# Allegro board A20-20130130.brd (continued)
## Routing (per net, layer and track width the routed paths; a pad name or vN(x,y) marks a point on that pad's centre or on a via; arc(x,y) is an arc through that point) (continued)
DSCK-N: length 90.5
  TOP w0.114: U4.G7 93.19,56.88 92.88,56.88 92.76,56.76 92.76,56.06 91.46,54.76 90.96,54.76 90.68,55.05 90.68,55.99 90.81,56.12 90.81,57.82 91.16,58.16 92.14,58.16 92.62,58.65 92.62,60.38 92.51,60.49 92.11,60.49 91.98,60.36 v1(91.98,60.26) ; v1(108.92,57.82) 108.98,57.82 109.06,57.9 109.19,57.9 109.24,57.86 109.24,57.69 108.85,57.3 108.64,57.3 108.44,57.5 108.44,58.47 108.2,58.71 107.64,58.71 107.18,58.25 107.18,54.45 107.55,54.08 108,54.08 109.15,55.23 109.15,56.09 109.68,56.62 U3.G7 ; v1(83.48,57.06) 83.1,56.68 U5.G7 ; v1(120.1,57.02) 120.11,57.02 U2.G7 ; v1(101.06,64.91) 101.38,64.91 101.57,65.09 101.57,65.47 C3.1 101.64,66 101.62,66.01 R9.2
  BOTTOM w0.114: v1(120.1,57.02) 119.87,57.26 118.56,57.26 118.37,57.45 109.56,57.45 109.19,57.82 v1(108.92,57.82) 108.92,58.11 108.39,58.63 108.39,59.81 107.95,60.25 107.52,60.25 107.21,60.55 107.21,61.53 107.09,61.65 106.91,61.65 106.79,61.54 106.79,60.55 106.49,60.25 105.31,60.25 104.56,61 104.13,61 103.45,61.68 103.45,62.12 103.82,62.48 103.82,62.65 103.69,62.78 103.52,62.78 103.15,62.41 102.72,62.41 101.94,63.2 101.94,64.56 101.84,64.65 101.55,64.65 101.48,64.72 101.48,65.01 101.57,65.1 101.81,65.1 101.94,65.22 101.94,65.81 101.73,66.01 100.73,66.01 100.57,65.85 100.57,65.04 100.7,64.91 v1(101.06,64.91) 101.06,64.55 101.23,64.37 101.23,62.02 100.09,60.88 100.09,60.71 101.45,59.35 101.45,58.92 101.13,58.61 100.69,58.61 99.33,59.96 98.59,59.96 97.6,58.97 97.6,57.98 97.31,57.69 96.87,57.69 96.54,58.02 96.54,58.97 96.42,59.09 95.84,59.09 94.47,60.46 92.18,60.46 v1(91.98,60.26) 91.72,60.53 91.45,60.53 90.47,59.54 87.7,59.54 87.41,59.83 86.61,59.83 86.08,59.3 86.08,57.93 85.53,57.38 83.78,57.38 83.48,57.09 v1(83.48,57.06)
EFUSE-VDDQ: length 0.5
  TOP w0.254: U1.T9 v1(99.43,76.1)
EGCLKIN: length 2.8
  TOP w0.102: U1.D13 v1(89.08,80.05)
  BOTTOM w0.102: 87.02,80.47 88.67,80.47 89.08,80.07 v1(89.08,80.05)
EGTXCLK: length 0.5
  TOP w0.102: U1.E12 v1(89.88,78.5)
EMDC: length 0.5
  TOP w0.102: U1.E10 v1(89.88,76.9)
EMDIO: length 2.8
  TOP w0.102: U1.D11 v1(89.08,77.7)
  BOTTOM w0.102: 87.02,78.12 88.67,78.12 89.08,77.71 v1(89.08,77.7)
EPHY-RST-N: length 0.5
  TOP w0.102: U1.C13 v1(88.28,80.05)
ERXCLK: length 2.8
  TOP w0.102: U1.D9 v1(89.08,76.1)
  BOTTOM w0.102: 87.02,76.52 88.67,76.52 89.08,76.11 v1(89.08,76.1)
ERXD0: length 0.5
  TOP w0.102: U1.E6 v1(89.88,73.7)
ERXD1: length 2.8
  TOP w0.102: U1.D6 v1(89.08,73.7)
  BOTTOM w0.102: 87.02,74.12 88.67,74.12 89.08,73.71 v1(89.08,73.7)
ERXD2: length 0.5
  TOP w0.102: U1.E5 v1(89.88,72.9)
ERXD3: length 2.8
  TOP w0.102: U1.D5 v1(89.08,72.9)
  BOTTOM w0.102: 87.02,73.32 88.67,73.32 89.08,72.91 v1(89.08,72.9)
ERXDV: length 2.8
  TOP w0.102: U1.D10 v1(89.08,76.9)
  BOTTOM w0.102: v1(89.08,76.9) 89.08,76.91 88.67,77.32 87.02,77.32
ESREXT: length 5.2
  TOP w0.102: U1.V21 v1(101.03,86.45)
  BOTTOM w0.102: 101.03,89.71 v1(101.03,86.45)
  BOTTOM w0.127: 101.03,91.12 101.03,89.71
ESRXM: length 1.5
  TOP w0.102: U1.U20 v1(100.23,85.65)
  BOTTOM w0.114: 99.84,86.49 99.84,86.48 99.84,86.04 v1(100.23,85.65)
ESRXP: length 0.6
  TOP w0.102: U1.U21 v1(100.23,86.45)
  BOTTOM w0.114: 100.16,86.52 v1(100.23,86.45)
ESTXM: length 4.9
  TOP w0.102: U1.T21 v1(99.43,86.45)
  BOTTOM w0.114: 98.94,90.59 99.33,90.19 99.33,86.55 v1(99.43,86.45)
ESTXP: length 5.7
  TOP w0.102: U1.T20 v1(99.43,85.65)
  BOTTOM w0.114: v1(99.43,85.65) 99.02,86.07 99.02,90.06 98.62,90.46
ESVDD1V2: length 1.1
  TOP w0.254: U1.M16 v1(95.48,82.45) ; U1.M15 v1(95.48,81.65)
ESVDD2V5: length 1.1
  TOP w0.254: U1.N16 v1(97.03,82.45) ; U1.N15 v1(97.03,81.65)
ETXD0: length 0.5
  TOP w0.102: U1.E8 v1(89.88,75.3)
ETXD1: length 2.8
  TOP w0.102: U1.D8 v1(89.08,75.3)
  BOTTOM w0.102: v1(89.08,75.3) 89.08,75.31 88.67,75.72 87.02,75.72
ETXD2: length 0.5
  TOP w0.102: U1.E7 v1(89.88,74.5)
ETXD3: length 2.8
  TOP w0.102: U1.D7 v1(89.08,74.5)
  BOTTOM w0.102: 87.02,74.92 88.67,74.92 89.08,74.51 v1(89.08,74.5)
ETXEN: length 0.5
  TOP w0.102: U1.E11 v1(89.88,77.7)
FMINL: length 2.8
  TOP w0.102: U1.Y20 v1(102.63,85.65)
  BOTTOM w0.102: v1(102.63,85.65) 102.63,85.64 103.04,85.23 104.69,85.23
FMINR: length 2.8
  TOP w0.102: U1.Y21 v1(102.63,86.45)
  BOTTOM w0.102: 104.69,86.03 103.04,86.03 102.63,86.44 v1(102.63,86.45)
GS-INT1: length 11.7
  TOP w0.102: 77.96,80.37 84.25,74.08 U1.A6
GY-INT1: length 0.5
  TOP w0.102: U1.C2 v1(88.28,70.5)
GY-INT2: length 14.2
  TOP w0.102: 76.34,71.39 81.74,71.39 83.37,69.76 86.7,69.76 87.09,69.36 88.73,69.36 89.45,70.08 U1.D1
HCEC: length 7.9
  TOP w0.102: 97.45,89.72 U1.P23
  TOP w0.127: 97.45,95.57 97.45,89.72
HHPD: length 8.9
  TOP w0.102: 97.87,89.72 97.87,87.27 97.86,87.26 97.83,87.26 U1.P22
  TOP w0.127: 97.87,89.72 97.87,95.57
HPBP: length 4.1
  TOP w0.102: U1.AC19 108.8,84.48
HPCOM: length 4.4
  TOP w0.102: U1.AA20 v1(103.43,85.65) ; U1.AA19 v1(103.43,84.85)
  BOTTOM w0.102: v1(103.43,84.85) 105.09,84.85 ; v1(103.43,85.65) 105.09,85.65
HPL: length 5
  TOP w0.178: U1.Y19 102.26,84.48 102.63,84.85 v1(102.63,84.85)
  BOTTOM w0.178: v1(102.63,84.85) 103.05,84.43 106.96,84.43
HPR: length 6
  TOP w0.178: v1(101.83,84.85) 101.83,84.82 101.49,84.48 U1.W19
  BOTTOM w0.178: 106.96,83.98 102.86,83.98 102.45,84.39 102.29,84.39 v1(101.83,84.85)
HPVCC: length 7.3
  TOP w0.102: 108.8,84.86 104.23,84.86 U1.AB19
  TOP w0.254: U1.J14 v1(93.06,80.87) U1.H15 ; U1.H9 v1(92.28,76.1) ; U1.J9 v1(93.08,76.1)
HSCL: length 7.9
  TOP w0.102: 98.25,89.72 U1.R23
  TOP w0.127: 98.25,95.57 98.25,89.72
HSDA: length 8.9
  TOP w0.102: 98.67,89.72 98.67,87.27 98.66,87.26 98.63,87.26 U1.R22
  TOP w0.127: 98.67,89.72 98.67,95.57
HTX0N: length 12.9
  TOP w0.114: 101.93,99.26 101.07,98.4 101.07,87.29 U1.V22
HTX0P: length 12.1
  TOP w0.114: U1.V23 100.75,87.78 100.75,98.53 101.61,99.39
HTX1N: length 0.6
  TOP w0.114: U1.U22 100.27,87.29
HTX1P: length 0.1
  TOP w0.114: 99.95,87.78 U1.U23
HTX2N: length 13
  TOP w0.114: U1.T22 99.44,87.26 99.44,98.76 98.78,99.41
HTX2P: length 11.9
  TOP w0.114: U1.T23 99.12,87.74 99.12,98.63 98.47,99.28
HTXCN: length 12.2
  TOP w0.114: U1.W22 101.87,87.29 101.87,97.43 102.92,98.48
HTXCP: length 11.4
  TOP w0.114: 102.6,98.61 101.55,97.56 101.55,87.78 U1.W23
HVP: length 0.5
  TOP w0.254: U1.T13 v1(99.43,80.05)
HVREGIO1: length 0.5
  TOP w0.254: U1.T14 v1(99.43,80.85)
I2S1-BCLK: length 0.5
  TOP w0.102: U1.D12 v1(89.08,78.5)
I2S1-MCLK: length 0.5
  TOP w0.102: U1.E9 v1(89.88,76.1)
IR-RX: length 10.4
  TOP w0.102: U1.A13 85.45,79.68 80.19,84.94 80.19,86.31
JTAG-CK: length 10.9
  TOP w0.102: 79.42,83.26 85,77.68 87.45,77.68 U1.B10
JTAG-DI: length 12.6
  TOP w0.102: U1.B9 87.43,76.9 84.77,76.9 78.13,83.54
JTAG-DO: length 12
  TOP w0.102: 77.83,83.28 84.63,76.48 U1.A9
JTAG-MS: length 11.4
  TOP w0.102: 78.35,83.8 84.88,77.28 U1.A10
JTAG-SEL: length 0.5
  TOP w0.254: U1.T10 v1(99.43,76.9)
LCD0-BL-EN: length 11.9
  TOP w0.102: U1.B4 87.59,72.48 87.21,72.85 84.05,72.85 78.4,78.5
LCD0-CLK: length 0.5
  TOP w0.102: U1.Y9 v1(102.63,76.1)
LCD0-D0: length 5.1
  TOP w0.102: U1.AB15 104.23,81.66 108.8,81.66
LCD0-D1: length 4.1
  TOP w0.102: U1.AC15 108.8,81.28
LCD0-D2: length 5.1
  TOP w0.102: 108.8,80.86 104.23,80.86 U1.AB14
LCD0-D3: length 4.1
  TOP w0.102: U1.AC14 108.8,80.48
LCD0-D4: length 5.1
  TOP w0.102: 108.8,80.06 104.23,80.06 U1.AB13
LCD0-D5: length 4.1
  TOP w0.102: U1.AC13 108.8,79.68
LCD0-D6: length 5.1
  TOP w0.102: U1.AB12 104.23,79.26 108.8,79.26
LCD0-D7: length 4.1
  TOP w0.102: U1.AC12 108.8,78.88
LCD0-D8: length 5.1
  TOP w0.102: 108.8,78.46 104.23,78.46 U1.AB11
LCD0-D9: length 4.1
  TOP w0.102: U1.AC11 108.8,78.08
LCD0-D10: length 0.5
  TOP w0.102: U1.Y15 v1(102.63,81.65)
LCD0-D11: length 2.2
  TOP w0.102: U1.AA15 v1(103.43,81.65)
  BOTTOM w0.102: v1(103.43,81.65) 105.09,81.65
LCD0-D12: length 2.8
  TOP w0.102: U1.Y14 v1(102.63,80.85)
  BOTTOM w0.102: 104.69,80.43 103.04,80.43 102.63,80.84 v1(102.63,80.85)
LCD0-D13: length 0.5
  TOP w0.102: U1.AA14 v1(103.43,80.85)
LCD0-D14: length 0.5
  TOP w0.102: U1.Y13 v1(102.63,80.05)
LCD0-D15: length 2.2
  TOP w0.102: U1.AA13 v1(103.43,80.05)
  BOTTOM w0.102: v1(103.43,80.05) 105.09,80.05
LCD0-D16: length 2.8
  TOP w0.102: U1.Y12 v1(102.63,78.5)
  BOTTOM w0.102: 104.69,78.08 103.04,78.08 102.63,78.49 v1(102.63,78.5)
LCD0-D17: length 0.5
  TOP w0.102: U1.AA12 v1(103.43,78.5)
LCD0-D18: length 2.8
  TOP w0.102: U1.Y11 v1(102.63,77.7)
  BOTTOM w0.102: 104.69,77.28 103.04,77.28 102.63,77.69 v1(102.63,77.7)
LCD0-D19: length 2.2
  TOP w0.102: U1.AA11 v1(103.43,77.7)
  BOTTOM w0.102: v1(103.43,77.7) 105.09,77.7
LCD0-D20: length 2.8
  TOP w0.102: U1.Y10 v1(102.63,76.9)
  BOTTOM w0.102: v1(102.63,76.9) 102.63,76.89 103.04,76.48 104.69,76.48
LCD0-D21: length 2.2
  TOP w0.102: U1.AA10 v1(103.43,76.9)
  BOTTOM w0.102: v1(103.43,76.9) 105.09,76.9
LCD0-D22: length 5.1
  TOP w0.102: U1.AB10 104.23,77.66 108.8,77.66
LCD0-D23: length 4.1
  TOP w0.102: U1.AC10 108.8,77.28
LCD0-DE: length 2.2
  TOP w0.102: U1.AA9 v1(103.43,76.1)
  BOTTOM w0.102: v1(103.43,76.1) 105.09,76.1
LCD0-HSYNC: length 5.1
  TOP w0.102: 108.8,76.86 104.23,76.86 U1.AB9
LCD0-PWR: length 2.2
  TOP w0.102: U1.C4 v1(88.28,72.1)
  BOTTOM w0.102: v1(88.28,72.1) 86.62,72.1
LCD0-SCK: length 2.2
  TOP w0.102: U1.C11 v1(88.28,77.7)
  BOTTOM w0.102: v1(88.28,77.7) 86.62,77.7
LCD0-SDA: length 2.2
  TOP w0.102: U1.C10 v1(88.28,76.9)
  BOTTOM w0.102: v1(88.28,76.9) 86.62,76.9
LCD0-VSYNC: length 4.1
  TOP w0.102: U1.AC9 108.8,76.48
LINEINL: length 0.7
  TOP w0.178: 104.41,85.66 104.02,85.28 U1.AB20
LINEINR: length 0.4
  TOP w0.178: U1.AB21 104.03,86.08 104.07,86.12 104.24,86.12
LRADC0: length 7.8
  TOP w0.102: 104.07,89.72 104.07,87.89 U1.AB23
  TOP w0.254: 104.07,95.36 104.07,89.72
LS-INT: length 2.8
  TOP w0.102: U1.D2 v1(89.08,70.5)
  BOTTOM w0.102: v1(89.08,70.5) 89.08,70.51 88.67,70.92 87.02,70.92
MIC1OUTN: length 7.9
  TOP w0.102: 104.65,89.72 U1.AC23
  TOP w0.127: 104.65,95.57 104.65,89.72
MICIN1: length 4.1
  TOP w0.102: U1.AC20 108.8,85.28
MICIN2: length 0.7
  TOP w0.102: U1.AC21 v1(105.38,86.08)
NALE: length 8.9
  TOP w0.102: 96.27,89.72 96.27,87.27 96.26,87.26 96.23,87.26 U1.M22
  TOP w0.127: 96.27,89.72 96.27,95.57
NAND-VCC: length 1.1
  TOP w0.102: U1.H19 v1(92.28,84.85) ; U1.J19 v1(93.08,84.85)
NCE0-N: length 7.9
  TOP w0.102: 94.25,89.72 U1.K23
  TOP w0.127: 94.25,95.57 94.25,89.72
NCE1-N: length 8.9
  TOP w0.102: U1.L22 95.47,87.3 95.47,89.72
  TOP w0.127: 95.47,95.57 95.47,89.72
NCE2-N: length 7.9
  TOP w0.102: 91.05,89.72 U1.F23
  TOP w0.127: 91.05,95.57 91.05,89.72
NCE3-N: length 8.9
  TOP w0.102: 91.45,89.72 91.45,87.27 U1.F22
  TOP w0.127: 91.45,89.72 91.45,95.57
NCLE: length 7.9
  TOP w0.102: 95.05,89.72 U1.L23
  TOP w0.127: 95.05,95.57 95.05,89.72
ND0: length 7.9
  TOP w0.102: 92.65,89.72 U1.H23
  TOP w0.127: 92.65,95.57 92.65,89.72
ND1: length 8.9
  TOP w0.102: 93.07,89.72 93.07,87.27 93.06,87.26 93.03,87.26 U1.H22
  TOP w0.127: 93.07,89.72 93.07,95.57
ND2: length 7.9
  TOP w0.102: 91.85,89.72 U1.G23
  TOP w0.127: 91.85,95.57 91.85,89.72
ND3: length 8.8
  TOP w0.102: U1.G22 92.24,87.26 92.24,89.72
  TOP w0.127: 92.24,89.72 92.24,95.57
ND4: length 2.4
  TOP w0.102: U1.H21 v1(92.28,86.45)
  BOTTOM w0.102: v1(92.28,86.45) 92.28,88.37
ND5: length 3
  TOP w0.102: U1.H20 v1(92.28,85.65)
  BOTTOM w0.102: v1(92.28,85.65) 92.28,85.74 91.89,86.12 91.89,87.94 91.88,87.96
ND6: length 2.4
  TOP w0.102: U1.G21 v1(91.48,86.45)
  BOTTOM w0.102: v1(91.48,86.45) 91.48,88.37
ND7: length 3
  TOP w0.102: U1.G20 v1(91.48,85.65)
  BOTTOM w0.102: v1(91.48,85.65) 91.48,85.74 91.09,86.12 91.09,87.94 91.08,87.96
NDQS: length 2.4
  TOP w0.102: U1.F21 v1(90.68,86.45)
  BOTTOM w0.102: v1(90.68,86.45) 90.68,88.37
NMI-N: length 0.5
  TOP w0.102: U1.F5 v1(90.68,72.9)
NRB0-N: length 7.9
  TOP w0.102: 93.45,89.72 U1.J23
  TOP w0.127: 93.45,95.57 93.45,89.72
NRB1-N: length 8.9
  TOP w0.102: U1.J22 93.83,87.26 93.86,87.26 93.87,87.27 93.87,89.72
  TOP w0.127: 93.87,89.72 93.87,95.57
NRE-N: length 8.9
  TOP w0.102: 94.67,89.72 94.67,87.27 94.66,87.26 94.63,87.26 U1.K22
  TOP w0.127: 94.67,89.72 94.67,95.57
NWE-N: length 7.9
  TOP w0.102: 95.85,89.72 U1.M23
  TOP w0.127: 95.85,95.57 95.85,89.72
NWP: length 2.4
  TOP w0.102: U1.M21 v1(95.48,86.45)
  BOTTOM w0.102: v1(95.48,86.45) 95.48,88.37
OSC24MI: length 7.9
  TOP w0.102: 96.65,89.72 U1.N23
  TOP w0.127: 96.65,95.57 96.65,89.72
OSC24MO: length 8.9
  TOP w0.102: 97.07,89.72 97.07,87.27 97.06,87.26 97.03,87.26 U1.N22
  TOP w0.127: 97.07,89.72 97.07,95.57
PA-SHDN-N: length 11.5
  TOP w0.102: 76.2,71.72 81.85,71.72 83.5,70.08 U1.A1
PC19: length 2.4
  TOP w0.102: U1.L21 v1(94.68,86.45)
  BOTTOM w0.102: v1(94.68,86.45) 94.68,88.37
PC20: length 2.4
  TOP w0.102: U1.K21 v1(93.88,86.45)
  BOTTOM w0.102: v1(93.88,86.45) 93.88,88.37
PC21: length 2.4
  TOP w0.102: U1.J21 v1(93.08,86.45)
  BOTTOM w0.102: v1(93.08,86.45) 93.08,88.37
PC22: length 3
  TOP w0.102: U1.J20 v1(93.08,85.65)
  BOTTOM w0.102: 92.68,87.96 92.69,87.94 92.69,86.12 93.08,85.74 v1(93.08,85.65)
PI10: length 2.2
  TOP w0.102: U1.C17 v1(88.28,83.25)
  BOTTOM w0.102: v1(88.28,83.25) 86.62,83.25
PI11: length 2.8
  TOP w0.102: U1.D17 v1(89.08,83.25)
  BOTTOM w0.102: 87.02,83.67 88.67,83.67 89.08,83.27 v1(89.08,83.25)
PI12: length 2.2
  TOP w0.102: U1.C16 v1(88.28,82.45)
  BOTTOM w0.102: v1(88.28,82.45) 86.62,82.45
PI14: length 2.2
  TOP w0.102: U1.C15 v1(88.28,81.65)
  BOTTOM w0.102: v1(88.28,81.65) 86.62,81.65
PI15: length 2.8
  TOP w0.102: U1.D15 v1(89.08,81.65)
  BOTTOM w0.102: 87.02,82.07 88.67,82.07 89.08,81.67 v1(89.08,81.65)
PLLDV: length 0.5
  TOP w0.254: U1.T16 v1(99.43,82.45)
PLLVP: length 0.5
  TOP w0.254: U1.P16 v1(97.83,82.45)
PLLVREG: length 0.5
  TOP w0.254: U1.R15 v1(98.63,81.65)
PWM0: length 9.2
  TOP w0.102: 80.99,86.31 80.99,85.16 85.67,80.48 U1.A14
RESET-N: length 2.2
  TOP w0.102: U1.C14 v1(88.28,80.85)
  BOTTOM w0.102: v1(88.28,80.85) 86.62,80.85
RTCVDD: length 0.5
  TOP w0.254: U1.K8 v1(93.88,75.3)
SA0: length 68.8
  TOP w0.102: v1(102.23,51.85) 102.54,52.16 102.54,53.98 102.79,54.24 102.79,56.69 102.66,56.82 102.66,62.58 104.13,64.04 104.13,64.98 v1(104.24,65.09) ; v1(79.48,53.86) 79.51,53.86 U5.K3 ; U2.K3 117.3,54.22 v1(116.9,53.83) ; U3.K3 106.39,53.86 v1(106.39,53.81) ; U4.K3 89.78,53.89 v1(89.76,53.89)
  TOP w0.127: U1.W4 v1(101.85,72.08)
  BOTTOM w0.102: v1(101.85,72.08) 102.25,71.68 102.25,71.11 102.25,71.1 102.25,69.81 104.49,67.57 104.49,65.52 104.25,65.28 104.25,65.1 v1(104.24,65.09) ; v1(116.9,53.83) 116.51,53.43 115.7,53.43 115.27,53 114.11,53 113.98,52.86 113.21,52.08 109.97,52.08 109,53.05 107.84,53.05 107.05,53.84 106.58,53.84 106.56,53.81 v1(106.39,53.81) 106.14,53.81 105.75,53.42 105.35,53.42 104.97,53.8 104.18,53.8 v1(102.23,51.85) 101.86,51.49 98.61,51.49 98.43,51.31 97.33,51.31 97.15,51.13 97.01,51.13 96.36,50.48 94.38,50.48 93.39,51.48 92.44,51.48 92.44,51.48 92.4,51.48 90.07,53.81 90.03,53.81 90.03,53.81 89.83,53.81 v1(89.76,53.89) 89.66,53.79 89.48,53.79 89.4,53.71 89.39,53.71 89.21,53.52 88.57,53.52 88.38,53.71 87.37,53.71 85.87,52.21 83.36,52.21 82.77,52.79 81.09,52.79 80.02,53.86 v1(79.48,53.86)
SA1: length 84.6
  TOP w0.102: v1(118.47,50.44) 118.48,50.44 119.22,51.18 119.22,52.38 120.26,53.42 U2.L7 ; U4.L7 93.16,53.48 92.22,52.55 92.22,48.94 91.89,48.6 91.89,48.07 v1(91.87,48.04) ; v1(108.16,49.41) 108.16,49.51 108.57,49.91 108.57,52.23 109.76,53.42 109.96,53.42 ; U5.L7 82.79,53.45 81.81,52.47 81.81,49.78 81.88,49.7 v1(81.88,49.67) ; v1(98.83,65.13) 98.83,63.57 99.21,63.18 99.21,63.18 99.6,62.8 99.6,54.88 99.54,54.82 99.54,54.15 100.09,53.59 100.09,49.73 99.71,49.35 v1(99.71,48.01)
  TOP w0.152: U1.R4 v1(98.65,72.08)
  BOTTOM w0.102: v1(81.88,49.67) 81.9,49.67 82.08,49.5 82.22,49.5 82.89,48.83 90.34,48.83 91.13,48.04 v1(91.87,48.04) 92.03,48.2 92.6,48.2 93.09,47.71 99.41,47.71 v1(99.71,48.01) 99.77,48.07 100.42,48.07 100.7,48.35 104.18,48.35 104.22,48.38 105.46,48.38 106.49,49.41 v1(108.16,49.41) ; v1(98.83,65.13) 98.26,65.69 98.26,70.85 98.26,70.85 98.26,71.68 v1(98.65,72.08) ; 108.26,49.31 110.28,49.31 110.93,48.66 114.64,48.66 114.65,48.65 115.86,48.65 116.43,49.22 117.23,49.22 117.99,49.98 118.02,49.98 118.47,50.43 v1(118.47,50.44)
  BOTTOM w0.152: v1(108.16,49.41) 108.26,49.31
SA2: length 69.5
  TOP w0.102: U2.L3 117.3,53.42 v1(116.9,53.03) ; 106.76,53.42 106.76,53.42 v1(106.39,53.05) ; v1(102.37,67.35) 102.37,65.2 100.82,63.65 100.82,55.32 100.98,55.16 100.98,53.37 101.26,53.09 101.26,52.49 100.88,52.11 v1(100.88,50.66) ; v1(89.76,53.1) 89.79,53.1 U4.L3 ; U5.L3 79.88,53.45 v1(79.48,53.06)
  TOP w0.127: U1.U4 v1(100.25,72.08)
  BOTTOM w0.102: v1(116.9,53.03) 116.51,52.63 115.76,52.63 115.52,52.39 114.65,52.39 113.73,51.47 109.72,51.47 108.75,52.44 107.51,52.44 106.97,52.97 106.47,52.97 106.4,53.05 v1(106.39,53.05) 106.32,52.97 106.17,52.97 106,52.81 106,52.81 105.91,52.72 105.86,52.72 105.76,52.62 104.46,52.62 102.68,50.84 101.17,50.84 100.99,50.66 v1(100.88,50.66) 99.82,50.66 99.81,50.65 97.53,50.65 97.41,50.52 97.26,50.52 96.61,49.87 94.13,49.87 93.13,50.87 92.14,50.87 89.91,53.1 v1(89.76,53.1) 89.65,53.1 89.46,52.91 89.45,52.91 89.2,52.67 88.66,52.67 88.38,52.39 87.8,52.39 86.45,51.04 83.66,51.04 82.52,52.18 80.73,52.18 80.27,52.65 79.86,53.06 v1(79.48,53.06) ; v1(102.37,67.35) 102.37,67.49 101.67,68.19 100.44,69.41 100.44,69.41 99.84,70.01 99.84,71.67 v1(100.25,72.08)
SA3: length 68.5
  TOP w0.102: v1(97.78,51.73) 97.78,52.11 97.84,52.16 97.84,53.05 97.31,53.57 97.2,53.69 v1(97.2,59.91) ; v1(88.99,53.9) 89.03,53.94 ; 89.03,53.94 89.03,53.95 89.37,54.28 89.37,54.29 ; 89.03,53.94 U4.K2 ; U5.K2 79.08,54.25 v1(78.68,53.86) ; v1(105.57,53.83) 105.96,54.22 U3.K2 ; v1(116.11,53.83) 116.5,54.22 U2.K2
  TOP w0.152: U1.M4 v1(95.45,72.08)
  BOTTOM w0.102: v1(78.68,53.86) 79.08,54.25 80.06,54.25 81.22,53.1 82.9,53.1 83.48,52.51 85.74,52.51 87.24,54.01 88.51,54.01 88.62,53.9 v1(88.99,53.9) 89.16,53.9 89.27,54.01 89.27,54.01 89.35,54.09 89.39,54.09 89.59,54.29 90.02,54.29 92.52,51.79 92.7,51.79 92.7,51.78 93.51,51.78 94.51,50.79 96.23,50.79 96.88,51.44 97.03,51.44 97.21,51.61 97.67,51.61 v1(97.78,51.73) 98.42,51.73 98.52,51.83 101.65,51.83 103.89,54.07 105.14,54.07 105.37,53.83 v1(105.57,53.83) 105.74,53.83 106.09,54.19 107.21,54.19 108.04,53.36 109.13,53.36 110.1,52.39 112.91,52.39 114.05,53.53 114.34,53.53 114.37,53.56 114.39,53.56 114.62,53.78 115.59,53.78 115.65,53.85 116.08,53.85 v1(116.11,53.83) ; v1(95.45,72.08) 95.9,71.63 95.9,65.56 97.56,63.9 97.56,60.28 v1(97.2,59.91)
SA4: length 91.1
  TOP w0.102: U4.L8 93.91,53.21 93.9,53.21 93.78,53.09 93.19,53.09 92.56,52.46 92.56,49.31 94.28,47.58 v1(94.28,47.31) ; v1(105.03,64.59) 104.73,64.3 104.73,63.78 103.32,62.37 103.32,57.03 103.39,56.96 103.39,53.97 103.16,53.74 103.16,51.4 102.59,50.84 102.59,48.9 v1(101.61,47.92) ; U2.L8 121.04,53.15 121.04,53.15 120.91,53.03 120.33,53.03 119.54,52.23 119.54,50.88 117.99,49.33 v1(117.95,49.33) ; 110.76,53.42 110.76,53.42 110.38,53.04 109.78,53.04 108.91,52.17 108.91,49.36 108.55,49.01 v1(107.47,49.01) ; U5.L8 83.5,53.05 82.92,53.05 82.92,53.05 82.9,53.05 82.35,52.5 82.35,49.07 82.99,48.43 83.02,48.43 v1(83.03,48.43)
  TOP w0.127: U1.Y4 v1(102.65,72.08)
  BOTTOM w0.102: v1(102.65,72.08) 103.06,71.67 103.06,69.89 103.86,69.09 105.3,67.65 105.3,64.88 105.03,64.6 v1(105.03,64.59) ; v1(83.03,48.43) 83.15,48.55 90.14,48.55 91.38,47.31 v1(94.28,47.31) 94.56,47.31 94.67,47.42 99.92,47.42 100.1,47.6 100.36,47.6 100.68,47.92 v1(101.61,47.92) 105.39,47.92 106.48,49.01 v1(107.47,49.01) 110.11,49.01 110.77,48.35 116.07,48.35 116.49,48.77 117.36,48.77 117.83,49.25 117.87,49.25 v1(117.95,49.33)
SA5: length 68.6
  TOP w0.102: U5.L2 79.08,53.45 v1(78.68,53.06) ; 105.96,53.42 105.96,53.42 v1(105.56,53.03) ; v1(88.97,53.09) 89.37,53.48 U4.L2 ; v1(116.11,53.03) 116.5,53.42 U2.L2 ; v1(99.64,51.07) 99.64,53.52 99.23,53.92 99.23,54.95 99.29,55.01 99.29,62.28 v1(98.09,63.49)
  TOP w0.127: U1.N4 v1(97.05,72.08)
  BOTTOM w0.102: v1(116.11,53.03) 115.72,53.03 115.39,52.69 114.4,52.69 113.48,51.78 109.84,51.78 108.87,52.75 107.63,52.75 106.98,53.4 106.58,53.4 106.55,53.43 106.19,53.43 105.88,53.11 105.87,53.11 105.79,53.03 v1(105.56,53.03) 105.49,52.95 104.36,52.95 102.56,51.14 100.77,51.14 100.7,51.07 v1(99.64,51.07) 99.07,51.07 99.01,51 97.46,51 97.28,50.83 97.13,50.83 96.48,50.18 94.26,50.18 93.26,51.17 92.27,51.17 89.96,53.48 89.61,53.48 89.53,53.4 89.52,53.4 89.33,53.22 89.32,53.22 89.19,53.09 v1(88.97,53.09) 88.4,53.09 88.08,53.4 87.5,53.4 86,51.9 83.23,51.9 82.65,52.49 80.96,52.49 80.62,52.83 80.62,52.83 80.09,53.37 80.07,53.37 80,53.44 79.74,53.44 79.73,53.45 79.09,53.45 78.69,53.06 v1(78.68,53.06) ; v1(98.09,63.49) 98.09,63.87 97.64,64.32 97.64,64.32 97.21,64.74 97.21,64.74 96.36,65.59 96.36,71.38 v1(97.05,72.08)
SA6: length 87.4
  TOP w0.102: v1(96.22,46.72) 96.22,47.24 93.77,49.69 93.77,52.24 94.17,52.64 ; v1(118.53,48.79) 118.53,48.79 120.1,50.36 120.1,51.96 120.37,52.22 120.91,52.22 121.03,52.35 121.04,52.35 U2.M8 ; 94.17,52.64 94.17,52.69 ; 94.17,52.64 94.18,52.64 U4.M8 ; v1(103.61,66.15) 103.61,65.68 103.56,65.63 103.48,65.55 103.48,64.26 102.07,62.85 102.07,56.51 102.25,56.33 102.25,54.56 101.89,54.2 101.89,52.54 101.34,51.99 101.34,50 100.4,49.06 100.4,46.92 v1(100.3,46.82) ; U3.M8 110.76,52.62 110.37,52.23 109.81,52.23 109.54,51.96 109.54,49.08 109.63,49 v1(109.63,48.22) ; v1(85.03,47.69) 85.03,47.91 83.51,49.44 83.51,51.68 83.49,51.7 83.49,52.25 U5.M8
  TOP w0.127: U1.V4 v1(101.05,72.08)
  BOTTOM w0.102: 96.09,46.78 96.1,46.79 96.12,46.79 96.14,46.77 99.87,46.77 99.89,46.74 100.22,46.74 v1(100.3,46.82) 100.34,46.82 100.54,47.02 105.45,47.02 106.63,48.2 109.6,48.2 v1(109.63,48.22) 109.65,48.2 110.08,48.2 110.18,48.09 110.19,48.09 110.54,47.75 116.54,47.75 116.88,48.09 117.84,48.09 118.53,48.79 v1(118.53,48.79) ; 96.09,46.78 95.44,46.78 95.26,46.6 91.05,46.6 89.96,47.69 v1(85.03,47.69) ; 96.09,46.78 96.14,46.72 v1(96.22,46.72) ; v1(103.61,66.15) 103.6,66.16 103.6,67.6 103.4,67.8 103.4,67.81 101.47,69.74 101.47,71.11 101.46,71.11 101.46,71.67 v1(101.05,72.08)
SA7: length 68.3
  TOP w0.102: U3.M2 105.96,52.62 v1(105.56,52.22) ; v1(116.11,52.22) 116.5,52.62 U2.M2 ; v1(88.97,52.27) 89.38,52.68 U4.M2 ; U5.M2 79.08,52.65 v1(78.68,52.26) ; v1(97.81,50.2) 97.33,50.68 97.33,51.93 97.55,52.14 97.55,52.85 96.82,53.58 96.82,60.12 97.13,60.44 v1(97.13,60.88)
  TOP w0.127: U1.M3 v1(95.45,71.28)
  BOTTOM w0.102: v1(116.11,52.22) 115.83,51.95 114.75,51.95 113.97,51.18 109.59,51.18 108.61,52.15 107.37,52.15 106.91,52.61 106.23,52.61 106.13,52.5 106.06,52.43 106,52.43 105.79,52.22 v1(105.56,52.22) 105.38,52.22 103.69,50.53 101.35,50.53 101.02,50.2 100.75,50.2 100.6,50.35 98.33,50.35 98.19,50.2 v1(97.81,50.2) 97.37,50.2 96.74,49.57 94,49.57 93.01,50.56 92.04,50.56 89.94,52.66 89.61,52.66 89.3,52.36 89.06,52.36 v1(88.97,52.27) 88.79,52.27 88.6,52.08 87.93,52.08 86.58,50.74 83.54,50.74 82.38,51.89 80.57,51.89 79.81,52.65 79.08,52.65 v1(78.68,52.26) ; v1(95.45,71.28) 95.45,65.52 97.22,63.75 97.22,61.35 97.13,61.26 v1(97.13,60.88)
SA8: length 86.8
  TOP w0.102: 94.16,51.61 94.16,51.37 94.17,51.36 94.17,49.81 96.82,47.16 v1(96.82,45.96) ; 94.16,51.61 94.18,51.62 U4.N8 ; 94.16,51.61 94.16,51.71 94.17,51.71 94.17,51.89 ; U3.N8 110.76,51.82 110.47,51.53 110.47,47.78 110.05,47.35 v1(110.05,47.04) ; U5.N8 83.89,51.85 83.88,51.86 83.88,49.52 85.46,47.94 85.46,47.4 85.35,47.29 v1(85.35,46.85) ; v1(100.68,46.04) 100.72,46.04 102.91,48.24 102.91,50.6 103.48,51.17 103.48,53.63 103.69,53.84 103.69,62.31 104.98,63.6 104.98,63.7 105.16,63.87 v1(105.16,63.95) ; v1(117.42,47.37) 117.45,47.4 118.24,47.4 120.82,49.97 120.82,51.34 121.03,51.55 121.04,51.55 U2.N8
  TOP w0.127: U1.AA3 v1(103.45,71.28)
  BOTTOM w0.102: v1(103.45,71.28) 103.45,71.27 103.45,70.04 105.61,67.88 105.61,64.4 v1(105.16,63.95) ; v1(117.42,47.37) 117.08,47.37 116.73,47.03 110.28,47.03 110.26,47.04 v1(110.05,47.04) 110.03,47.06 108.99,47.06 108.7,47.36 106.79,47.36 105.67,46.24 100.93,46.24 100.74,46.05 100.69,46.05 v1(100.68,46.04) 100.68,46.04 100.59,45.96 v1(96.82,45.96) 96.78,45.92 90.74,45.92 89.71,46.95 85.84,46.95 85.74,46.85 v1(85.35,46.85)
SA9: length 70.3
  TOP w0.102: U3.M3 106.76,52.59 v1(106.38,52.21) ; 90.17,52.69 90.17,52.68 89.76,52.28 89.76,52.27 ; U5.M3 79.88,52.65 v1(79.47,52.25) ; 89.76,52.27 v1(89.76,52.26) ; 89.76,52.27 U4.M3 ; U2.M3 117.3,52.62 v1(116.9,52.22) ; v1(99.59,49.92) 99.16,50.36 99.16,53.45 98.49,54.12 98.49,55.79 98.56,55.85 98.56,61.73 v1(98.14,62.14)
  TOP w0.152: U1.P4 v1(97.85,72.08)
  BOTTOM w0.102: v1(116.9,52.22) 116.27,51.59 115.1,50.42 114.03,50.42 113.89,50.28 111.52,50.28 110.94,50.86 109.47,50.86 108.51,51.82 107.14,51.82 106.75,52.21 v1(106.38,52.21) 106.35,52.21 105.96,51.82 105.39,51.82 103.8,50.23 101.47,50.23 101.18,49.94 99.67,49.94 99.66,49.92 v1(99.59,49.92) 98.14,49.92 97.99,49.77 97.37,49.77 96.87,49.26 93.88,49.26 92.88,50.26 91.94,50.26 91.92,50.27 91.9,50.27 91.89,50.28 91.87,50.28 89.89,52.26 v1(89.76,52.26) 89.66,52.26 89.18,51.78 88.21,51.78 86.86,50.43 86.71,50.43 86.71,50.43 83.41,50.43 82.27,51.57 80.41,51.57 79.73,52.25 v1(79.47,52.25) ; v1(98.14,62.14) 98.78,62.78 98.78,64.04 98.43,64.39 97.46,65.36 97.46,71.68 v1(97.85,72.08)
SA10: length 91.6
  TOP w0.102: v1(96.78,62.84) 96.8,62.84 97.38,62.27 97.38,61.18 97.6,60.96 97.6,53.72 98.22,53.1 98.22,49.7 97.98,49.46 v1(97.98,48.94) ; U3.H7 109.54,55.4 109.54,54.96 107.17,52.58 107.17,51.25 106.66,50.75 106.61,50.75 v1(106.5,50.64) ; U4.H7 90.57,53.08 90.57,50.83 90.58,50.82 v1(90.58,50.44) ; U5.H7 80.36,53.11 80.36,51.34 79.84,50.82 v1(79.84,50.78) ; v1(117.84,52.24) 117.84,53.16 120.5,55.82 U2.H7
  TOP w0.152: U1.L3 v1(94.65,71.28)
  BOTTOM w0.102: v1(117.84,52.24) 117.84,51.74 116.89,50.79 116.39,50.79 115.41,49.81 114.28,49.81 114.09,49.62 111.32,49.62 110.69,50.25 109.18,50.25 108.22,51.22 107.51,51.22 107.21,50.91 106.69,50.91 106.5,50.72 v1(106.5,50.64) 106.09,50.64 105.45,49.99 104.53,49.99 103.87,49.33 100.39,49.33 100.26,49.2 98.4,49.2 98.14,48.94 v1(97.98,48.94) 97.73,48.94 97.45,48.65 93.52,48.65 92.52,49.65 91.68,49.65 91.67,49.66 91.41,49.66 90.91,50.17 90.86,50.17 v1(90.58,50.44) 90.31,50.17 90.28,50.17 89.91,49.8 83.18,49.8 82.04,50.94 80.46,50.94 80.42,50.9 79.95,50.9 v1(79.84,50.78) ; v1(96.78,62.84) 96.78,62.86 94.65,64.99 v1(94.65,71.28)
SA11: length 84.7
  TOP w0.102: v1(108.93,48.6) 108.93,48.67 109.23,48.97 109.23,52.09 109.76,52.62 U3.M7 ; v1(95.09,47) 95.09,47.3 94.94,47.45 94.94,47.47 94.72,47.69 94.7,47.69 92.9,49.49 92.9,52.22 93.37,52.68 ; U4.M7 93.37,52.68 ; 93.37,52.68 93.37,52.69 ; v1(83.67,48.04) 83.61,48.1 83.61,48.39 82.68,49.32 82.68,52.24 U5.M7 ; U1.W3 v1(101.85,71.28) ; U2.M7 120.38,52.62 119.83,52.07 119.83,50.62 118.17,48.97 118.17,48.97 v1(117.77,48.58) ; v1(104.06,65.7) 103.78,65.43 103.78,64.14 102.38,62.73 102.38,56.67 102.52,56.53 102.52,54.39 102.22,54.1 102.22,52.44 101.64,51.86 101.64,49.8 100.75,48.91 100.75,47.92 100.86,47.82 v1(100.86,47.43)
  BOTTOM w0.102: v1(117.77,48.58) 117.61,48.41 116.63,48.41 116.26,48.04 110.66,48.04 110.1,48.6 v1(108.93,48.6) 106.62,48.6 105.45,47.43 v1(100.86,47.43) 100.72,47.29 100.23,47.29 100.02,47.09 98.55,47.09 98.54,47.1 95.19,47.1 v1(95.09,47) 94.99,46.9 91.28,46.9 89.98,48.2 83.82,48.2 v1(83.67,48.04) ; v1(101.85,71.28) 101.85,70.9 101.85,70.89 101.85,69.78 104.11,67.52 104.11,65.65 v1(104.06,65.7)
SA12: length 84.9
  TOP w0.102: U2.K7 120.15,54.22 118.59,52.66 118.59,51.89 117.53,50.83 v1(117.53,50.69) ; v1(98.89,48.78) 98.89,49.43 98.84,49.48 98.84,53.34 98.2,53.98 98.2,61.33 98.13,61.4 v1(98.13,61.43) ; U4.K7 93.09,54.28 91.6,52.8 91.6,49.92 91.38,49.69 91.38,49.64 v1(91.11,49.37) ; v1(107.69,50.56) 107.69,50.67 107.93,50.92 107.93,52.44 109.72,54.22 U3.K7 ; v1(80.97,50.41) 81.03,50.47 81.03,52.61 82.68,54.26 83.08,54.26 83.09,54.25 U5.K7
  TOP w0.152: U1.P3 v1(97.85,71.28)
  BOTTOM w0.102: v1(80.97,50.41) 81.06,50.41 81.35,50.7 81.84,50.7 83.07,49.48 90.25,49.48 90.41,49.64 90.84,49.64 v1(91.11,49.37) 92.37,49.37 93.39,48.35 98.34,48.35 98.77,48.78 v1(98.89,48.78) 99.37,48.78 99.42,48.83 100.36,48.83 100.48,48.96 103.91,48.96 104.5,49.55 105.53,49.55 106.23,50.24 107.36,50.24 107.68,50.56 v1(107.69,50.56) 107.71,50.53 108.42,50.53 109.04,49.91 110.6,49.91 111.21,49.3 114.2,49.3 114.41,49.5 115.57,49.5 116.47,50.4 117.11,50.4 117.34,50.62 117.47,50.62 v1(117.53,50.69) ; v1(98.13,61.43) 99.22,62.53 99.22,64.18 97.85,65.55 v1(97.85,71.28)
SA13: length 69
  TOP w0.102: v1(102.07,49.8) 102.07,50.97 102.85,51.74 102.85,53.86 103.09,54.11 103.09,56.82 102.96,56.95 102.96,62.45 104.42,63.91 104.42,64.73 v1(104.8,65.1) ; U5.N3 79.88,51.85 v1(79.48,51.46) ; U4.N3 90.17,51.88 v1(89.77,51.49) ; v1(116.9,51.42) 117.3,51.82 U2.N3 ; U3.N3 v1(106.36,51.42)
  TOP w0.152: 79.88,51.86 79.88,51.86 v1(79.48,51.46) ; U1.Y3 v1(102.65,71.28) ; 90.17,51.89 90.17,51.88
  BOTTOM w0.102: v1(104.8,65.1) 104.8,65.11 104.88,65.2 104.88,67.61 104.31,68.18 103.36,69.14 103.36,69.14 102.65,69.84 v1(102.65,71.28) ; v1(116.9,51.42) 116.86,51.38 116.55,51.38 115.28,50.11 114.16,50.11 114.01,49.96 111.41,49.96 110.81,50.56 109.34,50.56 108.38,51.51 106.83,51.51 106.74,51.42 v1(106.36,51.42) 105.5,51.42 103.87,49.8 v1(102.07,49.8) 101.47,49.8 101.31,49.63 100.26,49.63 100.15,49.52 98.26,49.52 98.15,49.41 97.44,49.41 96.96,48.93 93.78,48.93 92.76,49.95 91.68,49.95 90.15,51.49 v1(89.77,51.49) 89.19,50.91 87.86,50.91 87.06,50.1 83.31,50.1 82.16,51.25 80.24,51.25 80.03,51.46 v1(79.48,51.46)
SA14: length 83.4
  TOP w0.102: 83.18,51.77 83.18,49.29 84.2,48.27 v1(84.2,47.48) ; 83.18,51.77 83.08,51.86 ; 83.18,51.77 83.18,51.78 U5.N7 ; v1(109.31,47.5) 109.45,47.5 110.1,48.15 110.1,51.68 U3.N7 ; v1(99.08,65.65) 99.08,65.6 99.23,65.45 99.23,63.9 99.92,63.21 99.92,54.77 99.84,54.69 99.84,54.31 100.4,53.75 100.4,49.5 100.09,49.2 100.09,47.59 99.57,47.07 v1(99.57,46.37) ; U2.N7 120.51,50.23 118.19,47.91 v1(118.19,47.91) ; v1(95.56,46.33) 95.56,46.34 95.55,46.36 95.55,47.33 93.37,49.5 93.37,51.53 93.38,51.54 U4.N7
  TOP w0.152: U1.R3 v1(98.65,71.28)
  BOTTOM w0.102: v1(84.2,47.48) 84.28,47.48 84.38,47.39 84.44,47.39 84.56,47.27 85.27,47.27 85.28,47.28 89.91,47.28 90.9,46.29 95.5,46.29 95.53,46.33 v1(95.56,46.33) 95.62,46.27 96.25,46.27 96.35,46.37 v1(99.57,46.37) 100.48,46.37 100.77,46.66 105.65,46.66 106.78,47.79 109.03,47.79 v1(109.31,47.5) 109.41,47.5 109.61,47.7 110.21,47.7 110.52,47.39 116.64,47.39 117.03,47.78 117.98,47.78 118.1,47.91 v1(118.19,47.91) ; v1(99.08,65.65) 98.95,65.77 98.95,66.34 98.85,66.44 98.85,69.14 98.65,69.34 v1(98.65,71.28)
SA15: length 104.9
  TOP w0.102: U5.J7 82.97,55.05 80.72,52.8 80.72,51.01 80.4,50.68 v1(80.4,50.47) ; U4.J7 93.01,55.08 90.91,52.98 90.91,50.65 90.97,50.6 90.97,50.28 90.91,50.23 90.91,50.21 90.46,49.75 90.46,46.1 90.62,45.94 v1(90.62,45.55) ; U3.J7 109.96,54.91 107.6,52.55 107.6,51.13 106.7,50.22 106.7,48.19 107.35,47.54 v1(107.35,46.91) ; v1(101.29,45.75) 101.32,45.78 101.32,45.79 103.27,47.74 103.27,50.32 103.81,50.86 103.81,53.37 104.04,53.59 104.04,62.13 104.58,62.67 104.59,62.67 v1(105.38,63.47) ; U2.J7 119.82,54.33 119.82,54.33 118.29,52.8 118.29,52.08 116.98,50.77 116.98,48.09 115.56,46.66 115.18,46.66 v1(115.17,46.64)
  TOP w0.127: U1.AA4 v1(103.45,72.08)
  BOTTOM w0.102: 90.6,45.55 90.61,45.54 101.1,45.54 101.29,45.74 v1(101.29,45.75) 101.3,45.75 101.42,45.87 105.82,45.87 106.86,46.91 v1(107.35,46.91) 108.72,46.91 108.97,46.66 115.15,46.66 v1(115.17,46.64) ; 90.6,45.55 v1(90.62,45.55) ; 90.6,45.55 89.48,46.67 88.86,46.67 88.66,46.46 84.36,46.46 80.4,50.43 v1(80.4,50.47) ; v1(103.45,72.08) 103.99,71.54 103.99,70 105.88,68.11 105.88,63.97 v1(105.38,63.47)
SBA0: length 66.5
  TOP w0.102: v1(96.82,52.41) 96.28,52.95 96.28,60.45 96.41,60.59 96.41,61.34 v1(96.69,61.61) ; v1(88.99,54.71) 89.37,55.08 U4.J2 ; U2.J2 116.5,55.02 v1(116.11,54.62) ; v1(105.55,54.64) 105.93,55.02 U3.J2 ; U5.J2 79.08,55.05 v1(78.68,54.66)
  TOP w0.127: U1.K3 v1(93.85,71.28)
  BOTTOM w0.102: v1(93.85,71.28) 93.85,64.44 v1(96.69,61.61) ; v1(78.68,54.66) 79.07,55.05 80.23,55.05 80.41,54.88 80.6,54.69 81.59,53.7 83.16,53.7 83.74,53.12 85.49,53.12 86.97,54.6 88.51,54.6 88.61,54.71 v1(88.99,54.71) 89.1,54.82 89.33,54.82 89.62,55.11 90.06,55.11 92.77,52.4 93.76,52.4 94.13,52.03 95.93,52.03 96.31,52.41 v1(96.82,52.41) 97.2,52.41 97.25,52.46 101.41,52.46 103.63,54.68 105.13,54.68 105.17,54.64 v1(105.55,54.64) 105.73,54.64 105.88,54.8 106,54.8 106.2,55 106.23,55 106.24,55.02 107.37,55.02 108.36,54.03 109.32,54.03 110.35,52.99 112.63,52.99 113.86,54.22 114.19,54.22 114.39,54.42 115.39,54.42 115.59,54.62 v1(116.11,54.62)
SBA1: length 90.6
  TOP w0.102: v1(81.38,50.06) 81.35,50.09 81.35,52.48 82.73,53.86 83.51,53.86 U5.K8 ; v1(107.46,49.83) 107.64,49.83 108.25,50.43 108.25,52.33 109.74,53.82 110.36,53.82 110.76,54.22 ; 121.3,54.22 U2.K8 ; 121.3,54.22 121.31,54.22 ; 121.3,54.22 120.9,53.82 120.2,53.82 118.91,52.53 118.91,51.56 118.68,51.34 v1(118.68,51.34) ; U4.K8 94.17,54.28 94.17,54.29 93.77,53.89 93.13,53.89 91.9,52.66 91.9,49.46 91.58,49.13 91.58,49.13 91.32,48.87 v1(91.32,48.62) ; v1(98.92,48.12) 98.92,48.17 98.51,48.59 98.51,53.24 97.91,53.83 97.91,61.02 97.67,61.26 97.67,62.63 96.82,63.47 v1(96.81,63.47) ; 110.76,54.22 U3.K8 ; 110.76,54.22 110.76,54.22
  TOP w0.127: U1.L4 v1(94.65,72.08)
  BOTTOM w0.102: v1(118.68,51.34) 118.64,51.3 118.64,51.24 117.2,49.79 116.49,49.79 115.66,48.96 114.77,48.96 114.77,48.96 111.11,48.96 110.43,49.64 108.92,49.64 108.43,50.13 107.88,50.13 107.58,49.83 v1(107.46,49.83) 106.45,49.83 105.43,48.81 104.21,48.81 104.06,48.65 100.58,48.65 100.45,48.53 99.51,48.53 99.1,48.12 v1(98.92,48.12) 98.72,48.12 98.64,48.04 93.27,48.04 92.66,48.65 91.35,48.65 v1(91.32,48.62) 90.99,48.62 90.47,49.14 82.99,49.14 81.9,50.23 81.54,50.23 v1(81.38,50.06) ; v1(96.81,63.47) 95.06,65.23 95.06,71.67 v1(94.65,72.08)
SBA2: length 68.7
  TOP w0.102: U5.J3 79.51,54.66 v1(79.48,54.66) ; U2.J3 117.3,55.02 v1(116.9,54.62) ; v1(106.36,54.62) 106.76,55.02 U3.J3 ; U4.J3 89.78,54.69 v1(89.77,54.69) ; v1(96.86,51.85) 97.13,52.13 97.13,52.13 97.27,52.27 97.27,52.55 96.57,53.25 96.57,60.3 96.74,60.47 96.74,61.08 97.11,61.45 97.11,61.85 v1(96.84,62.12)
  TOP w0.152: U1.K4 v1(93.85,72.08)
  BOTTOM w0.102: v1(93.85,72.08) 94.26,71.67 94.26,64.71 v1(96.84,62.12) ; v1(79.48,54.66) 80.09,54.66 81.34,53.4 83.03,53.4 83.61,52.82 85.62,52.82 87.11,54.32 89.15,54.32 89.23,54.4 89.27,54.4 89.56,54.69 v1(89.77,54.69) 90.05,54.69 92.63,52.11 93.62,52.11 94.64,51.09 96.09,51.09 v1(96.86,51.85) 97.15,52.15 101.57,52.15 103.8,54.37 105.26,54.37 105.4,54.23 105.7,54.23 105.97,54.5 106.23,54.5 106.35,54.62 v1(106.36,54.62) 107.2,54.62 108.17,53.66 109.26,53.66 110.23,52.69 112.76,52.69 113.93,53.86 114.27,53.86 114.5,54.09 115.46,54.09 115.6,54.23 116.51,54.23 v1(116.9,54.62)
SCAS: length 65.8
  TOP w0.102: U3.G3 106.76,56.62 v1(106.36,56.22) ; U5.G3 79.88,56.65 v1(79.48,56.26) ; v1(89.77,56.29) 90.17,56.69 U4.G3 ; v1(102.8,66.89) 102.66,66.75 102.66,65.06 101.12,63.53 101.12,55.58 v1(101.57,55.13) ; U2.G3 117.3,56.62 v1(116.9,56.22) 116.91,56.22
  TOP w0.127: U1.U3 v1(100.25,71.28)
  BOTTOM w0.102: v1(116.9,56.22) 116.52,55.84 113.68,55.84 113.15,55.31 113.15,54.81 112.26,53.91 110.83,53.91 109.79,54.95 108.83,54.95 107.56,56.22 v1(106.36,56.22) 106.06,56.22 105.69,55.85 105.36,55.85 105.02,56.2 104.35,56.2 103.87,56.69 102.34,56.69 101.95,56.3 101.95,55.51 101.74,55.3 101.73,55.3 v1(101.57,55.13) 100.99,54.55 100.99,54.24 100.42,53.67 92.79,53.67 90.18,56.29 v1(89.77,56.29) 89.5,56.29 89.14,55.93 88.77,55.93 88.61,56.09 86.68,56.09 86.26,55.67 86.26,55.19 85.69,54.62 82.01,54.62 80.37,56.26 v1(79.48,56.26) ; v1(100.25,71.28) 100.25,70.09 102.79,67.55 102.79,66.9 v1(102.8,66.89)
SCK: length 3.3
  TOP w0.114: R8.1 100.93,68.07 100.93,68.4 100.82,68.51 100.53,68.51 100.47,68.58 100.47,68.77 100.55,68.85 100.8,68.85 100.93,68.98 100.93,69.24 100.72,69.45 100.72,70.01 U1.V1
SCK-N: length 3.5
  TOP w0.114: R9.1 101.25,68.11 101.25,69.37 101.04,69.58 101.04,70.49 U1.V2
SCKE: length 78.1
  TOP w0.102: v1(87.07,57.15) 87.11,57.11 87.11,56.2 86.83,55.92 86.48,55.92 85.56,56.83 84.85,56.83 84.7,56.68 U5.G9 ; U4.G9 94.98,56.66 v1(95.44,56.2) ; v1(98.91,55.34) 98.91,62.01 v1(98.12,62.8) ; v1(122.59,55.42) 122.59,56.14 U2.G9 122.11,56.62 ; U3.G9 v1(112.08,56.62)
  TOP w0.152: U1.N3 v1(97.05,71.28) ; 84.7,56.68 84.68,56.66
  BOTTOM w0.102: v1(97.05,71.28) 96.86,71.08 96.86,65.53 97.34,65.05 97.34,65.05 98.49,63.9 98.49,63.18 v1(98.12,62.8) ; v1(87.07,57.15) 87.76,57.15 87.77,57.16 88,57.16 88.25,57.42 89.6,57.42 89.66,57.48 90.42,57.48 92.93,54.98 94.06,54.98 94.18,55.1 94.85,55.1 95.44,55.68 v1(95.44,56.2) 95.87,56.2 95.99,56.08 95.99,54.74 96.1,54.63 96.27,54.63 96.39,54.75 96.39,56.44 96.5,56.55 96.73,56.55 96.8,56.47 96.8,54.77 96.92,54.65 97.09,54.65 97.21,54.76 97.21,56.46 97.28,56.54 97.52,56.54 97.61,56.45 97.61,54.76 97.71,54.67 97.88,54.67 98.02,54.81 98.02,56.34 98.15,56.47 99.17,56.47 99.32,56.32 99.32,56.14 99.11,55.92 98.98,55.92 98.92,55.86 98.92,55.35 v1(98.91,55.34) 99.16,55.34 99.3,55.21 99.56,55.21 101.98,57.63 104.46,57.63 104.72,57.37 105.01,57.37 105.2,57.56 105.2,57.97 105.44,58.2 107.06,58.2 108.95,56.32 111.77,56.32 v1(112.08,56.62) 113.17,56.62 113.48,56.93 118.19,56.93 118.67,56.45 119.09,56.45 119.21,56.33 119.21,55.95 119.33,55.83 119.5,55.83 119.62,55.95 119.62,56.33 119.74,56.45 120.17,56.45 120.77,55.85 121.4,55.85 121.82,55.42 v1(122.59,55.42)
SCS: length 76.2
  TOP w0.102: v1(101.38,53.79) 101.38,54.33 101.96,54.92 101.96,56.1 101.75,56.32 101.75,62.95 103.18,64.39 103.18,65.64 103.12,65.71 v1(103.12,66.41) ; U2.H2 116.5,55.82 v1(116.11,55.42) ; U4.H2 88.99,55.5 v1(88.97,55.5) ; U3.H2 105.92,55.82 v1(105.55,55.45) ; v1(78.68,55.46) 79.08,55.85 U5.H2
  TOP w0.152: U1.V3 v1(101.05,71.28)
  BOTTOM w0.102: v1(116.11,55.42) 115.99,55.54 113.81,55.54 113.45,55.18 113.45,54.68 112.38,53.61 110.67,53.61 109.63,54.65 108.63,54.65 107.45,55.83 106.1,55.83 105.82,55.55 105.69,55.55 105.59,55.45 v1(105.55,55.45) 105.26,55.45 104.81,55.89 104.17,55.89 104.03,56.03 104.03,56.03 103.81,56.25 103.59,56.25 103.47,56.13 103.47,55.82 103.57,55.72 103.84,55.72 103.92,55.64 103.92,55.49 103.85,55.42 103.54,55.42 103.38,55.26 103.22,55.26 103.14,55.34 103.14,56.36 103.05,56.45 102.95,56.45 102.84,56.34 102.84,55.3 102.88,55.26 102.88,54.91 102.81,54.83 102.66,54.83 102.56,54.94 102.56,56.19 102.49,56.26 102.29,56.26 102.18,56.16 102.18,55.3 102.15,55.26 102.15,54.92 102.48,54.59 102.48,54.4 102.31,54.24 102.22,54.24 101.77,54.7 101.63,54.7 101.47,54.54 101.47,54.41 101.7,54.18 101.72,54.18 101.93,53.97 101.93,53.77 101.73,53.57 101.59,53.57 v1(101.38,53.79) 101.38,53.76 101.07,53.46 100.64,53.46 100.44,53.26 96.09,53.26 95.52,52.69 94.39,52.69 93.96,53.12 92.91,53.12 90.15,55.88 89.52,55.88 89.27,55.63 89.14,55.5 v1(88.97,55.5) 88.8,55.5 88.52,55.79 86.77,55.79 86.56,55.57 86.56,55.05 85.82,54.32 81.86,54.32 80.31,55.87 78.64,55.87 78.52,55.74 78.52,55.62 v1(78.68,55.46) ; v1(101.05,71.28) 101.05,69.72 103.09,67.68 103.27,67.5 103.27,66.56 v1(103.12,66.41)
SD0-CLK: length 3
  TOP w0.102: U1.L20 v1(94.68,85.65)
  BOTTOM w0.102: 94.28,87.96 94.29,87.94 94.29,86.12 94.68,85.74 v1(94.68,85.65)
SD0-CMD: length 0.5
  TOP w0.102: U1.L19 v1(94.68,84.85)
SD0-D0: length 0.5
  TOP w0.102: U1.M19 v1(95.48,84.85)
SD0-D1: length 3
  TOP w0.102: U1.M20 v1(95.48,85.65)
  BOTTOM w0.102: v1(95.48,85.65) 95.48,85.74 95.1,86.12 95.1,87.94 95.08,87.96
SD0-D2: length 0.5
  TOP w0.102: U1.K19 v1(93.88,84.85)
SD0-D3: length 3
  TOP w0.102: U1.K20 v1(93.88,85.65)
  BOTTOM w0.102: 93.48,87.96 93.49,87.94 93.49,86.12 93.88,85.74 v1(93.88,85.65)
SD0-DET-N: length 12.5
  TOP w0.102: 78.13,80.67 84.31,74.49 87.44,74.49 U1.B6
SD1-CLK: length 0.5
  TOP w0.102: U1.E2 v1(89.88,70.5)
SD1-CMD: length 0.6
  TOP w0.102: U1.E1 89.86,69.69 v1(89.86,69.64)
SD1-D0: length 0.5
  TOP w0.102: U1.E3 v1(89.88,71.3)
SD1-D1: length 0.5
  TOP w0.102: U1.E4 v1(89.88,72.1)
SD1-D2: length 0.5
  TOP w0.102: U1.F3 v1(90.68,71.3)
SD1-D3: length 0.5
  TOP w0.102: U1.F4 v1(90.68,72.1)
SD1-DET-N: length 2.2
  TOP w0.102: U1.C6 v1(88.28,73.7)
  BOTTOM w0.102: v1(88.28,73.7) 86.62,73.7
SD3-CLK: length 6
  TOP w0.102: 84.5,87.74 84.5,86.02 86.46,84.06 87.47,84.06 U1.B18
SD3-CMD: length 5.1
  TOP w0.102: U1.A18 86.36,83.68 84.06,85.98 84.06,87.12
SD3-D0: length 6.2
  TOP w0.102: U1.A17 86.22,82.88 83.43,85.67 83.43,87.12
SD3-D1: length 6.6
  TOP w0.102: 83.76,87.12 83.76,85.83 86.31,83.27 87.45,83.27 U1.B17
SD3-D2: length 7.1
  TOP w0.102: U1.A16 86.08,82.08 82.69,85.47 82.69,86.83
SD3-D3: length 7.5
  TOP w0.102: 83.09,86.83 83.09,85.51 86.12,82.48 87.45,82.48 U1.B16
SD3-DET-N: length 12.6
  TOP w0.102: 77.92,78.03 83.71,72.24 83.71,72.24 83.89,72.05 87.47,72.05 U1.B3
SDQ0: length 26.7
  TOP w0.102: U2.C8 121.31,59.83 121.69,60.21 122.58,60.21 122.9,60.54 122.9,61.58 110.9,73.59 106.7,73.59 105.41,74.88 U1.AC7
  TOP w0.127: 121.31,59.82 121.31,59.83
SDQ1: length 25.8
  TOP w0.102: U2.C2 116.51,59.94 116.5,59.94 116.5,60.07 116.9,60.46 116.9,60.79 116.9,60.79 116.9,61.26 116.9,61.26 116.9,61.67 117.08,61.85 117.85,61.85 117.91,61.91 117.91,62.15 117.77,62.29 116.9,62.29 116.86,62.33 116.86,62.51 117.06,62.71 117.06,62.71 117.06,62.88 116.67,63.27 116.09,63.27 115.94,63.42 115.94,63.55 116.16,63.77 116.16,63.86 116.01,64.01 115.86,64.01 115.66,63.81 115.55,63.81 115.44,63.92 115.44,64.09 115.58,64.23 115.58,64.4 115.46,64.52 115.29,64.52 115.15,64.38 114.98,64.38 114.86,64.5 114.86,64.67 115,64.81 115,64.98 114.88,65.1 114.71,65.1 114.57,64.96 114.4,64.96 114.28,65.08 114.28,65.25 114.42,65.39 114.42,65.56 114.3,65.68 114.13,65.68 113.99,65.54 113.82,65.54 113.7,65.66 113.7,65.83 113.84,65.97 113.84,66.14 113.72,66.26 113.55,66.26 113.41,66.12 113.24,66.12 113.12,66.24 113.12,66.41 113.26,66.55 113.26,66.72 113.14,66.84 112.97,66.84 112.83,66.7 112.66,66.7 108.45,70.91 108.45,71.21 108.36,71.3 108.1,71.3 107.89,71.08 107.88,71.08 107.8,71 107.66,71 107.45,71.21 107.27,71.21 107.07,71 106.86,71 106.6,71.26 106.26,71.26 105.05,72.48 U1.AC4
SDQ2: length 30.6
  TOP w0.102: U1.AC8 105.77,75.68 107.09,74.36 111.16,74.36 123.58,61.94 123.58,58.81 122.58,57.81 122.28,57.81 122.27,57.81 121.72,57.81 U2.E8
  TOP w0.127: 121.31,58.22 U2.E8
SDQ3: length 25.8
  TOP w0.102: U2.B3 117.39,60.62 117.39,60.62 117.8,60.62 117.83,60.59 118.11,60.59 118.2,60.69 118.2,60.98 118.08,61.09 117.95,61.09 117.83,61.21 117.83,61.38 117.95,61.5 118.08,61.5 118.2,61.62 118.2,62.29 116.2,64.3 113.03,67.46 112.86,67.46 112.74,67.34 112.57,67.34 112.45,67.46 112.45,67.63 112.57,67.75 112.57,67.92 112.45,68.04 112.28,68.04 112.16,67.92 111.99,67.92 111.87,68.04 111.87,68.21 111.99,68.33 111.99,68.5 111.87,68.62 111.7,68.62 111.58,68.5 111.41,68.5 111.29,68.62 111.29,68.79 111.41,68.91 111.41,69.08 111.29,69.2 111.12,69.2 111,69.08 110.83,69.08 110.71,69.2 110.71,69.36 110.84,69.49 110.84,69.66 110.71,69.78 110.55,69.78 110.42,69.65 110.25,69.65 110.13,69.78 110.13,69.94 110.26,70.07 110.26,70.24 110.13,70.36 109.97,70.36 109.84,70.23 109.67,70.23 109.55,70.36 109.55,70.52 109.68,70.65 109.68,70.82 109.56,70.94 109.39,70.94 109.26,70.81 109.1,70.81 108.97,70.93 108.97,71.1 109.1,71.23 109.1,71.39 108.88,71.62 106.34,71.62 105.08,72.88 104.25,72.88 U1.AB5
SDQ4: length 25.8
  TOP w0.102: U2.C7 120.64,59.82 120.65,59.82 120.74,59.82 120.9,59.98 120.9,60.87 120.74,61.02 120.21,61.02 120.03,61.2 120.03,63.9 110.7,73.23 106.55,73.23 105.4,74.38 105.38,74.38 105.29,74.48 104.25,74.48 U1.AB7
SDQ5: length 30.6
  TOP w0.102: U2.E7 120.72,58.43 120.72,58.44 120.91,58.63 121.47,58.63 121.47,58.63 122.26,58.63 123.24,59.61 123.24,61.76 111.06,73.93 106.88,73.93 105.54,75.28 104.25,75.28 U1.AB8
SDQ6: length 25.9
  TOP w0.102: U1.AB4 104.25,72.08 105.02,72.08 106.37,70.72 108.16,70.72 114.09,64.79 114.09,64.62 113.81,64.34 113.81,64.18 113.93,64.05 114.1,64.05 114.38,64.33 114.55,64.33 114.67,64.21 114.67,64.04 114.39,63.76 114.39,63.6 114.51,63.47 114.68,63.47 114.96,63.75 115.13,63.75 115.25,63.63 115.25,63.46 114.97,63.19 114.97,63.02 115.09,62.9 115.26,62.9 115.54,63.17 115.7,63.17 115.94,62.94 116.46,62.94 116.59,62.81 116.59,62.5 116.48,62.39 115.27,62.39 115.08,62.2 115.08,59.86 115.29,59.65 115.31,59.65 115.54,59.42 116.29,59.42 116.5,59.21 116.51,59.2 U2.D2
SDQ7: length 27
  TOP w0.102: U1.AC3 104.86,71.68 106.17,70.37 108.01,70.37 113.51,64.87 113.51,63.99 113.81,63.7 113.81,63.53 113.53,63.25 113.53,63.08 113.65,62.96 113.82,62.96 114.1,63.24 114.26,63.24 114.62,62.88 114.62,62.65 114.45,62.49 113.56,62.49 113.44,62.36 113.44,62.24 113.56,62.11 114.52,62.11 114.62,62.01 114.62,61.84 114.5,61.72 113.47,61.72 113.35,61.61 113.35,61.44 113.47,61.32 114.5,61.32 114.62,61.2 114.62,58.33 115.11,57.84 116.68,57.84 117.06,58.22 U2.E3
SDQ8: length 16.1
  TOP w0.102: U1.AA1 103.05,69.23 105.32,66.95 105.64,66.95 105.79,67.11 106.03,67.11 106.18,67.26 106.49,67.26 107.53,66.22 107.53,66.14 107.53,66.06 107.82,65.77 107.9,65.77 107.98,65.77 108.27,65.48 108.27,65.4 108.27,65.31 108.56,65.02 108.64,65.02 108.72,65.03 109.07,64.69 109.07,64.37 108.91,64.22 108.13,64.22 107.46,63.55 107.46,60.79 106.91,60.23 106.57,60.23 106.16,59.82 U3.C2
SDQ9: length 16.5
  TOP w0.102: U3.C8 110.76,59.82 111.16,60.22 112.02,60.22 112.36,60.56 112.36,62.04 112.08,62.33 111.95,62.33 111.79,62.49 111.79,63 111.55,63.24 111.36,63.24 111.27,63.33 111.27,63.78 111.39,63.9 111.76,63.9 111.86,64 111.86,64.15 111.7,64.31 111.39,64.31 111.27,64.43 111.27,64.86 106.93,69.2 105.68,69.2 105.61,69.28 104.81,70.08 U1.AC1
SDQ10: length 16.7
  TOP w0.102: U1.Y1 102.25,69.68 102.4,69.54 102.4,68.99 105.32,66.07 106.39,66.07 106.77,65.68 106.77,65.36 106.91,65.22 107.27,65.22 107.45,65.04 107.45,64.91 107.36,64.82 106.49,64.82 106.43,64.76 106.43,64.51 106.51,64.42 106.9,64.42 107,64.32 107,64.19 106.73,63.91 106.51,63.91 106.43,63.84 106.43,63.03 106.16,62.76 106.16,62.32 106.36,62.13 106.36,60.46 106.15,60.25 106.12,60.25 106.12,60.25 105.76,60.25 105.55,60.04 105.55,59.44 105.69,59.3 105.69,59.3 U3.D2
SDQ11: length 17.2
  TOP w0.102: U3.C7 110.2,59.82 110.36,59.97 110.36,61.63 110.06,61.92 110.06,62.21 110.26,62.41 111.26,62.41 111.43,62.58 111.43,62.77 111.35,62.85 110.76,62.85 110.61,62.99 110.61,63.22 110.91,63.51 110.91,64.74 106.78,68.86 105.28,68.86 104.25,69.9 104.25,70.48 104.09,70.64 104.09,70.64 U1.AB2
SDQ12: length 18.5
  TOP w0.102: U3.E7 109.96,58.22 110.13,58.39 110.37,58.63 111.71,58.63 112.02,58.94 112.02,59.42 112.63,60.03 112.63,63.99 107.07,69.56 105.97,69.56 U1.AC2
  TOP w0.127: 104.65,70.88 U1.AC2
SDQ13: length 18
  TOP w0.102: U1.W2 101.45,70.88 101.85,70.48 101.85,69.58 102.14,69.3 102.14,68.79 105.24,65.69 106.28,65.69 106.4,65.57 106.4,65.4 106.14,65.14 106.1,65.1 106.1,63.1 104.37,61.36 104.37,59.16 104.91,58.62 106.12,58.62 106.51,58.22 U3.E3
  TOP w0.127: 106.76,58.22 U3.E3
SDQ14: length 20.6
  TOP w0.102: U3.E8 111.16,57.82 112.5,57.82 112.92,58.25 112.92,64.22 107.17,69.98 106.13,69.98 104.82,71.28 104.25,71.28 U1.AB3
SDQ15: length 16.1
  TOP w0.102: U3.B3 107.18,61.04 107.18,61.83 107.1,61.9 106.74,61.9 106.63,62.01 106.63,62.24 106.71,62.31 107.11,62.31 107.18,62.38 107.18,62.58 107.14,62.62 106.88,62.62 106.78,62.72 106.78,62.83 106.84,62.89 106.98,62.89 107.09,63 107.09,63.13 107.01,63.21 106.9,63.21 106.78,63.33 106.78,63.47 108,64.69 108,65.06 106.69,66.37 106.34,66.37 106.27,66.44 106.27,66.62 106.14,66.75 105.89,66.75 105.82,66.69 105.82,66.52 105.72,66.42 105.39,66.42 102.65,69.16 102.65,70.48 102.53,70.6 102.53,70.6 U1.Y2
SDQ16: length 15.2
  TOP w0.102: U1.T2 99.07,70.86 99.41,70.86 99.45,70.82 99.45,69.47 99.26,69.28 99.26,67.59 97.74,66.07 97.74,65.14 97.3,64.7 96.37,64.7 95.59,63.93 95.59,62.69 95.27,62.37 95.1,62.37 94.79,62.68 94.62,62.68 94.5,62.56 94.5,62.4 94.81,62.08 94.81,61.92 94.6,61.7 94.6,60.47 94.4,60.28 94.3,60.28 94.17,60.14 94.17,59.89 U4.C8
SDQ17: length 15.3
  TOP w0.102: U1.N2 97.05,70.48 97.05,68.79 93.1,64.84 93.1,64.49 91.95,63.34 90.37,63.34 89.78,62.75 89.78,60.29 89.72,60.23 89.72,60.23 U4.C2
SDQ18: length 17.2
  TOP w0.102: U4.E8 94.44,58.29 94.86,57.86 95.48,57.86 95.88,58.27 95.88,60.5 96.13,60.75 96.13,61.96 96.3,62.13 96.3,63.67 96.65,64.02 97.65,64.02 98.4,64.77 98.4,65.77 99.87,67.24 99.87,68.88 100.25,69.27 100.25,70.48 U1.U2
SDQ19: length 15.2
  TOP w0.102: U1.P1 97.38,70 97.38,68.65 93.44,64.72 93.44,64.37 91.68,62.61 91.51,62.61 91.17,62.96 91,62.96 90.88,62.84 90.88,62.67 91.22,62.32 91.22,62.16 91.11,62.04 90.87,62.04 90.37,62.55 90.24,62.55 90.1,62.41 90.1,62.21 90.59,61.72 90.59,61.1 U4.B3
  TOP w0.127: 90.17,60.69 U4.B3
SDQ20: length 15.3
  TOP w0.102: U4.C7 93.73,59.89 93.78,59.94 93.78,60.89 93.61,61.06 93.61,61.15 93.78,61.32 93.78,61.75 93.65,61.88 93.44,61.88 93.36,61.96 93.36,62.11 93.77,62.52 94.07,62.52 94.23,62.67 94.23,62.87 94.57,63.22 94.7,63.22 95.07,62.84 95.2,62.84 95.33,62.97 95.33,63.12 94.98,63.46 94.98,63.63 95.27,63.91 95.27,64.1 96.19,65.03 97.17,65.03 97.43,65.28 97.43,66.26 98.96,67.79 98.96,69.41 99.05,69.5 U1.T1
SDQ21: length 16.1
  TOP w0.102: U4.E7 93.37,58.29 93.37,58.49 93.57,58.69 95.37,58.69 95.52,58.84 95.52,60.57 95.8,60.85 95.8,62.23 95.93,62.35 95.93,63.78 96.51,64.36 97.41,64.36 98.05,65.01 98.05,65.91 99.57,67.42 99.57,69.15 99.85,69.44 U1.U1
SDQ22: length 16.8
  TOP w0.102: U4.D2 89.37,59.09 89.37,59.09 88.98,59.49 88.19,59.49 87.74,59.94 87.74,61.26 90.2,63.73 91.83,63.73 92.73,64.63 92.73,64.95 96.65,68.87 U1.N1
SDQ23: length 19.7
  TOP w0.102: U1.M2 96.25,70.48 96.25,68.92 92.37,65.04 92.37,64.71 91.74,64.08 90.07,64.08 87.41,61.41 87.41,59.07 87.79,58.69 89.55,58.69 89.95,58.29 U4.E3
SDQ24: length 25.1
  TOP w0.102: U5.C2 79.29,59.86 79.4,59.96 79.4,59.96 79.69,60.25 80.1,60.25 80.28,60.07 80.28,59.68 80.34,59.62 80.7,59.62 81.39,60.31 81.39,60.62 81.15,60.87 81.15,60.87 80.61,61.4 80.61,62.43 81.26,63.07 83.17,63.07 83.42,63.32 83.42,63.55 83.21,63.77 83.21,63.9 83.32,64.02 83.7,64.02 83.79,64.11 83.79,64.31 83.72,64.39 83.27,64.39 83.22,64.44 83.22,64.59 83.21,64.6 83.33,64.72 83.69,64.72 83.79,64.82 83.79,65 83.7,65.1 83.39,65.1 83.34,65.14 83.34,65.36 83.47,65.49 83.68,65.49 85.33,67.15 90.93,67.15 92.13,68.34 92.13,68.35 93.45,69.67 U1.J1
